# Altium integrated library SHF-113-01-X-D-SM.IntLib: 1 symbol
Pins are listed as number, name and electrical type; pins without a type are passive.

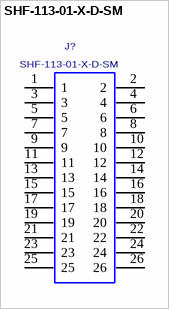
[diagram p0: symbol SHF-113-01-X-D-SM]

## SHF-113-01-X-D-SM
designator J?
0.05"X0.05" SHROUDED TERMINAL STRIP, 26PINS.; MANUFACTURER: SAMTEC
footprint SHF-113-01-X-D-SM
pins: 1, 2, 3, 4, 5, 6, 7, 8, 9, 10, 11, 12, 13, 14, 15, 16, 17, 18, 19, 20, 21, 22, 23, 24, 25, 26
